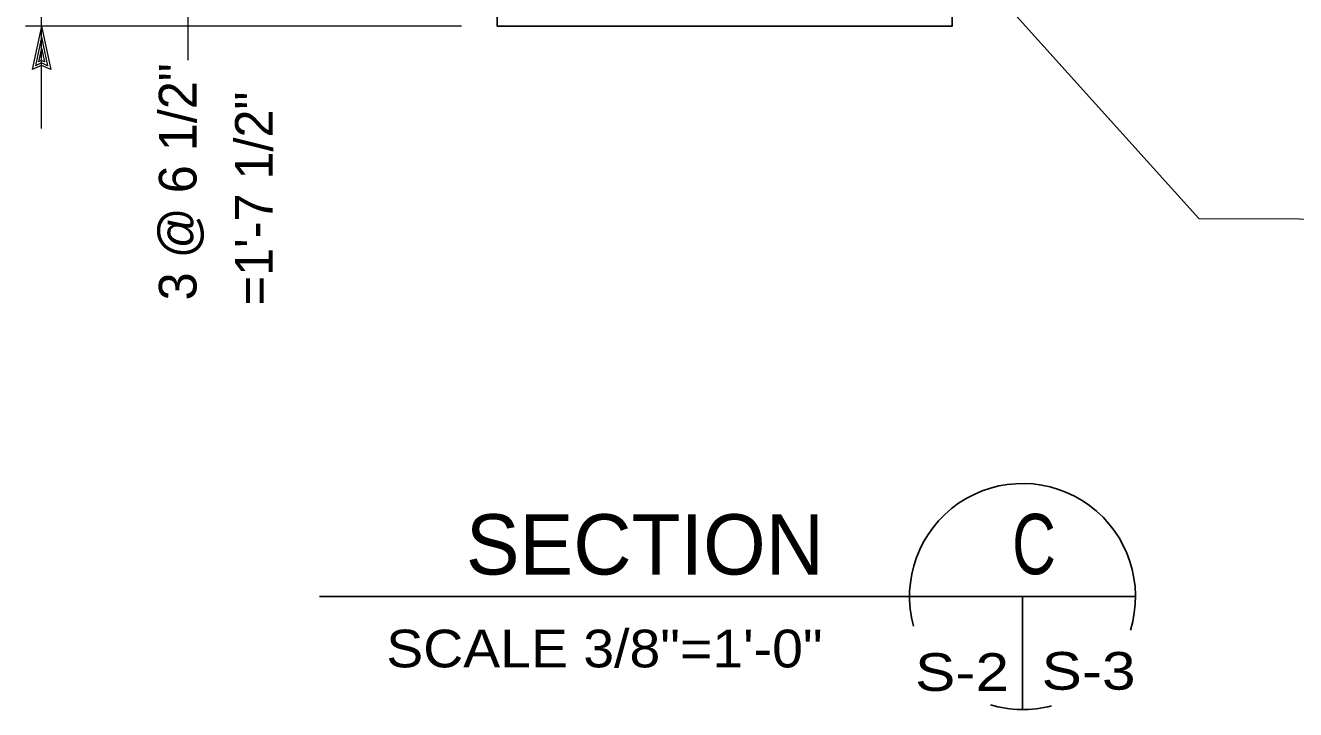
# Model space of a CAD drawing. Extents: x -28.1 to 13.9, y -16.1 to 13.9.
# Drawn here: x -4.181 to 0.036, y 0.807 to 3.076 of the extents above; entities that cross this region are included whole.
import ezdxf
from ezdxf.enums import TextEntityAlignment as Align

# ---------------------------------------------------------------- set-up
doc = ezdxf.new("R2010")
doc.units = 0
doc.header["$LTSCALE"] = 0.05
doc.layers.add('1', color=7, linetype='Continuous', lineweight=13)

msp = doc.modelspace()

# ---------------------------------------------------------------- linework, layer by layer
at = {"layer": '1', "lineweight": 25}
for p, q in [((-2.61504, 3.07369), (-2.61504, 3.96269)), ((-1.10504, 3.07269), (-1.10504, 3.64169)), ((-2.61504, 3.07369), (-1.10604, 3.07369)), ((-3.20504, 1.18169), (-0.49604, 1.18169)), ((-0.87104, 1.18169), (-0.87104, 0.80669))]:
    msp.add_line(p, q, dxfattribs=at)
at = {"layer": '1'}
for p, q in [((-2.73304, 3.07369), (-4.18104, 3.07369)), ((-4.12804, 3.07369), (-4.15904, 2.92969)), ((-4.12804, 3.03669), (-4.14804, 2.94269)), ((-4.12804, 3.07369), (-4.09704, 2.92969)), ((-4.12804, 3.03669), (-4.10804, 2.94269)), ((-4.12804, 3.00069), (-4.13704, 2.95569)), ((-4.12804, 3.00069), (-4.11804, 2.95569)), ((-4.12804, 2.95169), (-4.14804, 2.94269)), ((-4.12804, 2.95969), (-4.13704, 2.95569)), ((-4.11804, 2.95569), (-4.12804, 2.95969)), ((-4.10804, 2.94269), (-4.12804, 2.95169))]:
    msp.add_line(p, q, dxfattribs=at)
for points in [[(-4.12804, 2.73469), (-4.12804, 3.07369), (-4.12804, 3.19769), (-4.12804, 10.47969), (-4.12804, 10.57569), (-4.12804, 10.97569)], [(-1.59712, 3.89047), (-0.28558, 2.43598), (0.38318, 2.43322)], [(-3.64104, 2.96069), (-3.64104, 3.28469), (-3.45904, 3.50069)], [(-4.09704, 2.92969), (-4.12804, 2.94369), (-4.15904, 2.92969)]]:
    msp.add_lwpolyline(points, dxfattribs=at)
at = {"layer": '1', "lineweight": 25}
for start, end in [(342.70891, 195.26862), (253.4742, 284.92162)]:
    msp.add_arc((-0.87104, 1.18169), 0.375, start, end, dxfattribs=at)

# ---------------------------------------------------------------- texts
at = {"layer": '1'}
msp.add_text('3 @ 6 1/2"', height=0.125, rotation=90, dxfattribs=at).set_placement((-3.61304, 2.95063), align=Align.RIGHT)
msp.add_text('=1\'-7 1/2"', height=0.125, rotation=90, dxfattribs=at).set_placement((-3.36004, 2.50198), align=Align.CENTER)
msp.add_text('SECTION', height=0.2, dxfattribs=at).set_placement((-2.12464, 1.25469), align=Align.CENTER)
for s, height, width, p in [('C', 0.2, 0.75, (-0.83289, 1.25569)), ('S-2', 0.125, 1.2, (-1.07168, 0.86869)), ('S-3', 0.125, 1.2, (-0.65168, 0.87269))]:
    msp.add_text(s, height=height, dxfattribs=dict(at, width=width)).set_placement(p, align=Align.CENTER)
at = {"layer": '1', "width": 1.1}
msp.add_text('SCALE 3/8"=1\'-0"', height=0.125, dxfattribs=at).set_placement((-2.98304, 0.94669))

doc.saveas('drawing.dxf')
